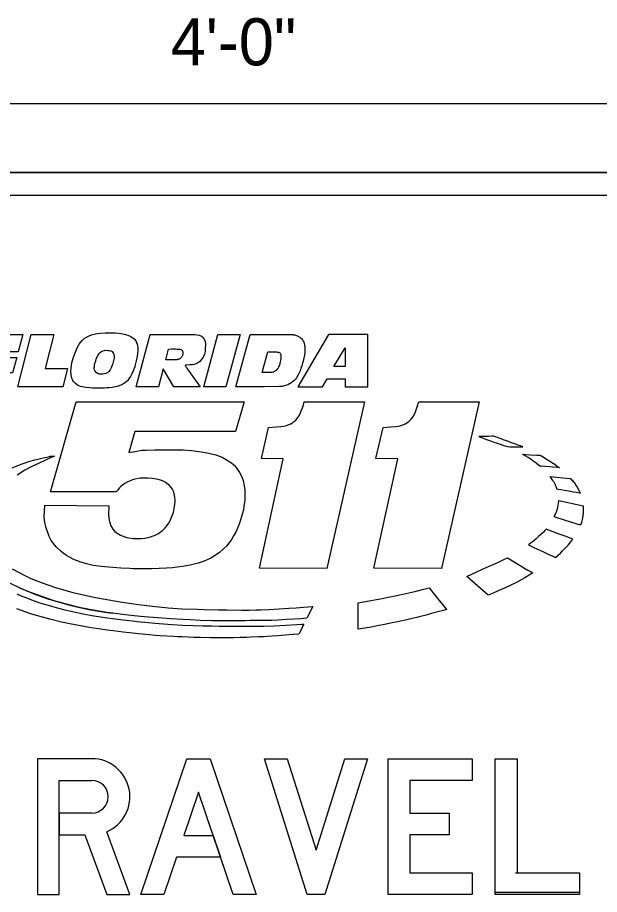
# Model space of a CAD drawing. Extents: x 0 to 770, y 0 to 495.
# Drawn here: x 288.4 to 331.6, y 418 to 483.1 of the extents above; entities that cross this region are included whole.
import ezdxf

# ---------------------------------------------------------------- set-up
doc = ezdxf.new("R2010")
doc.units = 0
for name, color, linetype in [('Default', 7, 'Continuous'), ('GSBWFill', 7, 'Continuous'), ('GSColorFill', 7, 'Continuous'), ('GSDims', 7, 'Continuous'), ('GSOutline', 7, 'Continuous'), ('TextStructures', 7, 'Continuous')]:
    doc.layers.add(name, color=color, linetype=linetype)

msp = doc.modelspace()

# ---------------------------------------------------------------- linework, layer by layer
at = {"layer": 'Default'}
for p, q in [((341.543, 471.587), (270.202, 471.587)), ((270.202, 471.587), (341.543, 471.587)), ((341.543, 469.888), (270.202, 469.888)), ((298.26, 459.55), (301.581, 459.55)), ((290.84, 447.861), (292.751, 454.562)), ((322.668, 454.562), (319.878, 442.183)), ((314.865, 442.202), (316.637, 450.318)), ((325.381, 419.568), (330.13, 419.568)), ((330.13, 419.568), (330.13, 418.091)), ((330.13, 418.091), (323.812, 418.091))]:
    msp.add_line(p, q, dxfattribs=at)
for points in [[(284.877, 459.55), (288.792, 459.55), (288.443, 458.266), (286.221, 458.266), (286.12, 457.838), (288.341, 457.838), (288.036, 456.702), (285.801, 456.702), (285.535, 455.679), (283.878, 455.679)], [(289.419, 459.55), (291.1, 459.55), (290.451, 457.019), (292.125, 457.019), (291.774, 455.679), (288.434, 455.679)], [(295.688, 459.671), (295.918, 459.656), (296.093, 459.636), (296.328, 459.59), (296.585, 459.512), (296.826, 459.411), (297.06, 459.241), (297.194, 459.074), (297.297, 458.846), (297.336, 458.596), (297.331, 458.404), (297.311, 458.14), (297.286, 457.939), (297.223, 457.605), (297.143, 457.296), (297.104, 457.161), (296.993, 456.852), (296.892, 456.635), (296.781, 456.434), (296.68, 456.264), (296.588, 456.148), (296.417, 455.988), (296.293, 455.903), (296.147, 455.827), (295.799, 455.699), (295.799, 455.699), (295.436, 455.63), (295.205, 455.603), (295.033, 455.588), (294.865, 455.577), (294.68, 455.569), (294.68, 455.569), (294.406, 455.565), (294.221, 455.568), (294.132, 455.571), (293.98, 455.578), (293.98, 455.578), (293.771, 455.594), (293.771, 455.594), (293.507, 455.621), (293.324, 455.646), (293.228, 455.66), (293.084, 455.697), (292.866, 455.796), (292.866, 455.796), (292.712, 455.907), (292.712, 455.907), (292.576, 456.049), (292.52, 456.143), (292.48, 456.224), (292.443, 456.313), (292.378, 456.57), (292.367, 456.833), (292.381, 457.027), (292.417, 457.293), (292.448, 457.459), (292.486, 457.622), (292.58, 457.937), (292.676, 458.198), (292.84, 458.569), (292.983, 458.832), (293.205, 459.116), (293.359, 459.246), (293.52, 459.347), (293.768, 459.47), (293.975, 459.547), (294.312, 459.626), (294.558, 459.655), (294.9, 459.68), (295.219, 459.687), (295.58, 459.678)], [(301.581, 459.55), (301.716, 459.542), (301.9, 459.504), (302.071, 459.424), (302.189, 459.32), (302.29, 459.148), (302.328, 459.024), (302.353, 458.855), (302.343, 458.44), (302.328, 458.283), (302.282, 458.091), (302.18, 457.862), (302.18, 457.862), (302.038, 457.662), (301.936, 457.558), (301.767, 457.429), (301.767, 457.429), (301.524, 457.326), (301.407, 457.312), (301.317, 457.303), (301.198, 457.293), (301.198, 457.293), (300.974, 457.281), (300.903, 457.28), (300.872, 457.279), (300.872, 457.273), (300.867, 457.257), (300.863, 457.256), (300.857, 457.25), (300.855, 457.234), (300.869, 457.211), (300.907, 457.156), (300.943, 457.105), (300.981, 457.052), (301.154, 456.808), (301.958, 455.679), (300.01, 455.679), (299.215, 456.998), (298.881, 455.679), (297.21, 455.679), (298.26, 459.55)], [(303.267, 459.55), (304.931, 459.55), (303.881, 455.679), (302.237, 455.679)], [(304.611, 455.679), (305.668, 459.55), (307.042, 459.564), (308.07, 459.56), (308.796, 459.55), (308.858, 459.546), (308.888, 459.542), (308.93, 459.536), (308.985, 459.525), (309.039, 459.511), (309.11, 459.489), (309.188, 459.458), (309.269, 459.418), (309.357, 459.364), (309.391, 459.34), (309.448, 459.289), (309.489, 459.247), (309.541, 459.184), (309.575, 459.134), (309.617, 459.063), (309.652, 458.987), (309.684, 458.891), (309.711, 458.773), (309.732, 458.638), (309.741, 458.541), (309.741, 458.341), (309.737, 458.283), (309.724, 458.16), (309.708, 458.041), (309.686, 457.91), (309.643, 457.709), (309.608, 457.575), (309.566, 457.429), (309.504, 457.226), (309.449, 457.059), (309.38, 456.868), (309.335, 456.752), (309.215, 456.503), (309.111, 456.34), (309.033, 456.236), (309.033, 456.236), (308.92, 456.121), (308.92, 456.121), (308.823, 456.039), (308.823, 456.039), (308.69, 455.944), (308.607, 455.894), (308.607, 455.894), (308.472, 455.826), (308.296, 455.758), (308.209, 455.733), (308.06, 455.701), (307.956, 455.687), (307.844, 455.68), (306.744, 455.666), (305.715, 455.665)], [(312.728, 455.679), (314.403, 455.679), (314.403, 459.55), (311.494, 459.55), (309.218, 455.679), (311.045, 455.679), (311.382, 456.255), (312.728, 456.255)], [(295.136, 458.377), (295.239, 458.358), (295.331, 458.33), (295.422, 458.29), (295.484, 458.221), (295.534, 458.139), (295.56, 458.058), (295.573, 457.94), (295.567, 457.834), (295.511, 457.529), (295.452, 457.324), (295.354, 457.076), (295.274, 456.928), (295.19, 456.81), (295.083, 456.711), (295.083, 456.711), (294.955, 456.651), (294.709, 456.606), (294.589, 456.604), (294.47, 456.615), (294.419, 456.626), (294.34, 456.656), (294.25, 456.72), (294.217, 456.755), (294.161, 456.831), (294.121, 456.919), (294.097, 457.035), (294.096, 457.095), (294.11, 457.189), (294.126, 457.276), (294.154, 457.4), (294.21, 457.606), (294.253, 457.74), (294.33, 457.928), (294.393, 458.05), (294.453, 458.138), (294.508, 458.201), (294.553, 458.243), (294.638, 458.303), (294.748, 458.351), (294.863, 458.376), (294.902, 458.381)], [(299.415, 457.67), (299.624, 458.471), (299.847, 458.48), (299.991, 458.482), (300.122, 458.48), (300.261, 458.476), (300.344, 458.471), (300.419, 458.464), (300.459, 458.455), (300.52, 458.438), (300.556, 458.423), (300.601, 458.396), (300.631, 458.366), (300.647, 458.343), (300.658, 458.322), (300.674, 458.271), (300.679, 458.246), (300.684, 458.211), (300.686, 458.165), (300.683, 458.119), (300.678, 458.087), (300.664, 458.035), (300.647, 457.994), (300.62, 457.943), (300.61, 457.929), (300.57, 457.871), (300.551, 457.847), (300.521, 457.816), (300.479, 457.777), (300.476, 457.775), (300.445, 457.751), (300.41, 457.73), (300.387, 457.718), (300.355, 457.705), (300.355, 457.705), (300.311, 457.695), (300.27, 457.688), (300.222, 457.683), (300.192, 457.68), (300.173, 457.678), (300.137, 457.676), (300.106, 457.675), (299.884, 457.674), (299.603, 457.672)], [(306.988, 458.266), (307.1, 458.267), (307.244, 458.268), (307.326, 458.269), (307.387, 458.269), (307.456, 458.267), (307.543, 458.263), (307.587, 458.26), (307.63, 458.256), (307.7, 458.248), (307.747, 458.242), (307.776, 458.238), (307.801, 458.231), (307.836, 458.215), (307.869, 458.192), (307.897, 458.162), (307.928, 458.108), (307.93, 458.102), (307.947, 458.046), (307.956, 458.003), (307.963, 457.952), (307.965, 457.902), (307.963, 457.852), (307.96, 457.817), (307.953, 457.754), (307.934, 457.627), (307.91, 457.513), (307.878, 457.393), (307.844, 457.289), (307.813, 457.205), (307.788, 457.145), (307.743, 457.058), (307.685, 456.978), (307.604, 456.893), (307.56, 456.858), (307.468, 456.799), (307.406, 456.769), (307.35, 456.748), (307.287, 456.731), (307.223, 456.722), (307.159, 456.721), (306.992, 456.721), (306.827, 456.721), (306.695, 456.721), (306.561, 456.721)], [(311.882, 457.186), (312.728, 458.575), (312.728, 457.186)], [(305.23, 454.562), (304.593, 452.346), (297.11, 452.346), (296.662, 450.798), (296.757, 450.813), (296.998, 450.849), (297.256, 450.888), (297.495, 450.925), (297.664, 450.951), (297.957, 450.96), (298.601, 450.977), (299.35, 450.988), (299.988, 450.991), (300.301, 450.99), (300.699, 450.979), (301.316, 450.925), (301.891, 450.857), (302.496, 450.764), (303.125, 450.606), (303.59, 450.44), (303.59, 450.44), (304.301, 450.017), (304.487, 449.846), (304.647, 449.669), (304.892, 449.315), (305.059, 448.969), (305.147, 448.704), (305.231, 448.303), (305.272, 447.982), (305.289, 447.639), (305.277, 447.248), (305.24, 446.924), (305.218, 446.794), (305.173, 446.522), (305.045, 446.038), (304.929, 445.676), (304.803, 445.344), (304.604, 444.882), (304.451, 444.586), (304.258, 444.278), (304.144, 444.121), (303.935, 443.866), (303.675, 443.598), (303.402, 443.361), (303.077, 443.128), (302.752, 442.936), (302.494, 442.81), (302.268, 442.717), (301.807, 442.569), (301.417, 442.468), (301.215, 442.422), (300.937, 442.365), (300.678, 442.32), (300.245, 442.261), (299.907, 442.228), (299.462, 442.202), (298.908, 442.174), (298.385, 442.157), (298.385, 442.157), (296.966, 442.158), (296.73, 442.165), (296.73, 442.165), (296.064, 442.206), (296.064, 442.206), (295.478, 442.25), (294.882, 442.303), (294.645, 442.326), (294.227, 442.369), (294.03, 442.404), (293.533, 442.518), (293.023, 442.677), (292.853, 442.739), (292.638, 442.825), (292.21, 443.037), (292.031, 443.145), (291.759, 443.332), (291.634, 443.43), (291.27, 443.778), (291.27, 443.778), (290.912, 444.262), (290.763, 444.538), (290.763, 444.538), (290.514, 445.273), (290.437, 445.62), (290.393, 445.972), (290.443, 446.874), (295.195, 446.818), (295.195, 446.818), (295.158, 446.144), (295.201, 445.768), (295.201, 445.768), (295.277, 445.499), (295.316, 445.399), (295.48, 445.098), (295.632, 444.921), (295.718, 444.844), (295.808, 444.785), (296.039, 444.655), (296.174, 444.593), (296.374, 444.519), (296.508, 444.479), (296.68, 444.439), (296.832, 444.414), (296.976, 444.399), (297.203, 444.388), (297.459, 444.388), (297.548, 444.393), (297.844, 444.428), (298.092, 444.478), (298.268, 444.525), (298.47, 444.594), (298.567, 444.632), (298.859, 444.781), (299.018, 444.886), (299.156, 444.992), (299.262, 445.086), (299.365, 445.19), (299.501, 445.35), (299.614, 445.507), (299.675, 445.61), (299.747, 445.743), (299.747, 445.743), (299.918, 446.15), (299.974, 446.33), (300.043, 446.633), (300.087, 446.96), (300.098, 447.113), (300.098, 447.281), (300.088, 447.417), (300.055, 447.639), (300.037, 447.718), (299.972, 447.912), (299.901, 448.056), (299.821, 448.181), (299.678, 448.347), (299.592, 448.423), (299.374, 448.576), (299.165, 448.68), (299.023, 448.731), (298.821, 448.787), (298.562, 448.841), (298.367, 448.867), (298.088, 448.884), (297.966, 448.892), (297.757, 448.892), (297.517, 448.875), (297.393, 448.858), (297.122, 448.803), (296.929, 448.747), (296.721, 448.67), (296.543, 448.58), (296.371, 448.479), (296.217, 448.385), (296.043, 448.247), (295.976, 448.164), (295.874, 448.041), (295.797, 447.946), (295.772, 447.915), (295.754, 447.893), (295.745, 447.884), (295.737, 447.877), (295.725, 447.869), (295.713, 447.865), (295.692, 447.862), (295.682, 447.861), (295.662, 447.861), (295.644, 447.861), (290.84, 447.861), (292.751, 454.562)], [(307.045, 452.644), (307.614, 452.685), (307.954, 452.724), (308.181, 452.756), (308.373, 452.796), (308.557, 452.859), (308.671, 452.911), (308.706, 452.93), (308.814, 452.994), (308.906, 453.059), (308.954, 453.097), (309.061, 453.193), (309.126, 453.262), (309.223, 453.381), (309.293, 453.485), (309.336, 453.561), (309.415, 453.731), (309.472, 453.882), (309.552, 454.108), (309.629, 454.339), (309.658, 454.43), (309.698, 454.562), (314.165, 454.562), (311.375, 442.183), (306.362, 442.202), (308.134, 450.318), (306.513, 450.337)], [(315.548, 452.644), (316.117, 452.685), (316.457, 452.724), (316.683, 452.756), (316.876, 452.796), (317.06, 452.859), (317.174, 452.911), (317.209, 452.93), (317.317, 452.994), (317.409, 453.058), (317.457, 453.096), (317.564, 453.193), (317.629, 453.262), (317.726, 453.381), (317.795, 453.485), (317.839, 453.561), (317.918, 453.731), (317.974, 453.882), (318.055, 454.108), (318.132, 454.339), (318.16, 454.43), (318.201, 454.562), (322.668, 454.562), (319.878, 442.183), (314.865, 442.202), (316.637, 450.318), (315.016, 450.336)], [(325.901, 451.209), (325.917, 451.21), (325.744, 451.273), (325.556, 451.342), (325.322, 451.428), (325.143, 451.493), (324.963, 451.559), (324.848, 451.601), (324.636, 451.679), (324.532, 451.717), (324.41, 451.761), (324.305, 451.8), (324.174, 451.848), (324.04, 451.897), (323.941, 451.933), (323.849, 451.967), (323.778, 451.993), (323.611, 451.99), (323.377, 451.986), (322.968, 451.979), (322.649, 451.973), (322.757, 451.934), (322.924, 451.873), (323.229, 451.762), (323.436, 451.687), (323.633, 451.615), (323.775, 451.562), (323.944, 451.501), (324.242, 451.399), (324.448, 451.332), (324.576, 451.292), (324.716, 451.249), (324.782, 451.23), (324.948, 451.219), (325.321, 451.205), (325.492, 451.203), (325.629, 451.204), (325.722, 451.205), (325.809, 451.206), (325.875, 451.208)], [(325.904, 450.656), (326.442, 450.625), (326.97, 450.594), (327.155, 450.583), (327.188, 450.581), (327.199, 450.58), (327.212, 450.578), (327.22, 450.577), (327.229, 450.575), (327.24, 450.571), (327.248, 450.568), (327.26, 450.563), (327.273, 450.557), (327.286, 450.549), (327.296, 450.543), (327.358, 450.504), (327.539, 450.392), (327.719, 450.28), (328.047, 450.077), (328.16, 450.007), (328.214, 449.973), (328.309, 449.903), (328.481, 449.775), (328.567, 449.711), (328.635, 449.661), (328.618, 449.662), (328.588, 449.664), (328.54, 449.668), (328.502, 449.671), (328.151, 449.698), (327.924, 449.715), (327.284, 449.764), (327.25, 449.768), (327.218, 449.773), (327.204, 449.777), (327.176, 449.79), (327.162, 449.8), (327.135, 449.819), (327.12, 449.831), (326.909, 449.992), (326.697, 450.154), (326.604, 450.224), (326.484, 450.303), (326.39, 450.364), (326.325, 450.405), (326.258, 450.446), (326.205, 450.479), (326.121, 450.53), (326.047, 450.573), (325.958, 450.625), (325.936, 450.638), (325.915, 450.65)], [(327.93, 449.017), (329.394, 448.863), (329.399, 448.863), (329.404, 448.863), (329.408, 448.862), (329.412, 448.862), (329.415, 448.861), (329.42, 448.861), (329.427, 448.859), (329.433, 448.858), (329.44, 448.856), (329.444, 448.855), (329.451, 448.852), (329.455, 448.851), (329.46, 448.848), (329.465, 448.845), (329.47, 448.842), (329.479, 448.836), (329.483, 448.832), (329.489, 448.827), (329.515, 448.8), (329.566, 448.744), (329.624, 448.677), (329.671, 448.62), (329.725, 448.552), (329.8, 448.451), (329.839, 448.395), (329.954, 448.216), (330.07, 447.988), (330.185, 447.762), (330.112, 447.775), (329.9, 447.811), (329.684, 447.848), (329.47, 447.885), (329.333, 447.908), (329.021, 447.962), (328.741, 448.01), (328.547, 448.043), (328.455, 448.059), (328.433, 448.122), (328.385, 448.256), (328.374, 448.288), (328.353, 448.347), (328.339, 448.384), (328.321, 448.426), (328.289, 448.495), (328.266, 448.539), (328.237, 448.589), (328.207, 448.635), (328.183, 448.671), (328.15, 448.715), (328.099, 448.785), (328.04, 448.867), (327.989, 448.936)], [(328.603, 447.215), (330.41, 446.838), (330.41, 446.607), (330.41, 446.376), (330.398, 446.245), (330.385, 446.14), (330.347, 445.904), (330.324, 445.809), (330.3, 445.709), (330.267, 445.578), (330.235, 445.476), (330.235, 445.476), (330.221, 445.45), (330.213, 445.438), (330.208, 445.431), (330.199, 445.422), (330.19, 445.414), (330.188, 445.412), (330.186, 445.411), (330.183, 445.41), (330.18, 445.409), (330.176, 445.408), (330.172, 445.408), (330.166, 445.409), (330.162, 445.41), (330.149, 445.412), (330.133, 445.417), (330.116, 445.422), (330.105, 445.426), (329.954, 445.473), (329.011, 445.771), (328.406, 445.962), (328.258, 446.008), (328.251, 446.01), (328.263, 446.037), (328.282, 446.079), (328.317, 446.159), (328.374, 446.289), (328.411, 446.373), (328.441, 446.445), (328.469, 446.527), (328.477, 446.556), (328.487, 446.594), (328.497, 446.642), (328.51, 446.707), (328.542, 446.883), (328.594, 447.163)], [(328.351, 442.986), (328.713, 443.322), (328.877, 443.483), (329.019, 443.628), (329.089, 443.702), (329.193, 443.817), (329.279, 443.913), (329.382, 444.032), (329.488, 444.157), (329.563, 444.249), (329.643, 444.348), (329.577, 444.373), (329.429, 444.428), (329.135, 444.536), (328.703, 444.695), (327.979, 444.963), (327.648, 445.085), (327.558, 444.992), (327.423, 444.857), (327.26, 444.7), (327.096, 444.548), (327.012, 444.472), (326.909, 444.384), (326.73, 444.236), (326.609, 444.139), (326.462, 444.025), (326.334, 443.93), (326.692, 443.763), (327.016, 443.611), (327.455, 443.405), (327.86, 443.216), (328.153, 443.079)], [(324.783, 442.957), (325.724, 442.398), (326.007, 442.23), (326.3, 442.056), (326.528, 441.921), (326.666, 441.839), (326.39, 441.673), (326.066, 441.479), (325.797, 441.323), (325.404, 441.116), (325.031, 440.932), (324.557, 440.715), (324.084, 440.511), (323.708, 440.348), (323.345, 440.191), (322.168, 441.229), (321.762, 441.587), (322.133, 441.755), (322.596, 441.965), (323.146, 442.214), (323.422, 442.34), (323.718, 442.474), (324.105, 442.649), (324.452, 442.806)], [(318.971, 440.734), (319.617, 439.929), (319.966, 439.493), (320.263, 439.123), (319.925, 439.033), (319.49, 438.916), (319.148, 438.824), (318.652, 438.691), (318.652, 438.691), (318.23, 438.578), (318.039, 438.527), (317.708, 438.452), (317.309, 438.363), (316.614, 438.212), (316.09, 438.103), (315.774, 438.039), (315.016, 437.889), (314.664, 437.822), (314.194, 437.74), (313.696, 437.652), (313.696, 438.111), (313.696, 438.636), (313.696, 438.941), (313.696, 439.621), (313.696, 439.621), (314.363, 439.737), (314.363, 439.737), (315.467, 439.941), (315.917, 440.029), (316.436, 440.133), (316.794, 440.208), (317.229, 440.306), (317.89, 440.462), (318.58, 440.633)]]:
    msp.add_lwpolyline(points, close=True, dxfattribs=at)
for points in [[(287.996, 449.652), (288.759, 449.935), (289.239, 450.113), (289.597, 450.212), (289.919, 450.297), (290.302, 450.39), (290.694, 450.479), (290.821, 450.506), (290.917, 450.522), (291.156, 450.522), (290.899, 450.411), (290.485, 450.227), (290, 450.005), (289.471, 449.754), (288.946, 449.468), (288.365, 449.108)], [(288.015, 442.138), (289.035, 441.604), (289.398, 441.439), (290.241, 441.097), (291.226, 440.767), (292.52, 440.396), (294.205, 440.009), (296.182, 439.661), (297.387, 439.49), (298.437, 439.367), (299.594, 439.258), (300.607, 439.186), (301.766, 439.144), (302.259, 439.129), (303.32, 439.102), (303.934, 439.09), (305.073, 439.075), (305.605, 439.082), (306.095, 439.093), (306.452, 439.104), (307.057, 439.128), (307.821, 439.167), (308.539, 439.215), (309.086, 439.252), (309.635, 439.29), (310.339, 439.337), (309.881, 438.47), (309.442, 438.441), (308.386, 438.372), (307.754, 438.33), (307.255, 438.32), (306.589, 438.309), (306.195, 438.304), (305.679, 438.298), (305.298, 438.295), (304.351, 438.29), (303.341, 438.291), (302.836, 438.293), (301.959, 438.319), (301.243, 438.348), (300.679, 438.375), (299.75, 438.431), (299.152, 438.473), (298.132, 438.556), (297.541, 438.611), (296.849, 438.681), (296.404, 438.73), (295.472, 438.841), (295.033, 438.9), (294.019, 439.065), (293.097, 439.253), (291.944, 439.539), (291.488, 439.668), (291.114, 439.78), (290.275, 440.057), (289.797, 440.229), (289.119, 440.493), (289.119, 440.493), (288.589, 440.714), (288.55, 440.731), (287.832, 441.079)], [(288.34, 440.282), (288.713, 440.124), (289.009, 440.005), (289.436, 439.843), (289.843, 439.698), (290.213, 439.576), (290.672, 439.435), (290.92, 439.364), (291.454, 439.219), (291.928, 439.1), (292.385, 438.993), (292.799, 438.901), (293.405, 438.778), (293.933, 438.681), (294.425, 438.599), (294.876, 438.532), (295.665, 438.424), (296.242, 438.352), (296.931, 438.272), (297.284, 438.234), (298.13, 438.151), (298.589, 438.11), (298.909, 438.084), (299.893, 438.013), (300.656, 437.968), (301.442, 437.931), (302.174, 437.911), (302.833, 437.9), (303.386, 437.893), (304.279, 437.884), (304.536, 437.883), (304.995, 437.881), (305.678, 437.88), (306.174, 437.881), (306.699, 437.888), (307.43, 437.919), (308.314, 437.961), (309.152, 438.004), (309.512, 438.024), (309.668, 438.033), (309.599, 437.9), (309.477, 437.665), (309.285, 437.297), (308.842, 437.26), (308.286, 437.217), (307.737, 437.176), (307.321, 437.146), (306.94, 437.12), (306.661, 437.102), (306.322, 437.085), (305.734, 437.061), (305.412, 437.05), (304.93, 437.036), (304.456, 437.027), (303.901, 437.021), (303.274, 437.019), (302.72, 437.023), (301.996, 437.036), (301.522, 437.049), (301.063, 437.065), (300.631, 437.083), (300.272, 437.1), (299.972, 437.116), (299.496, 437.145), (299.005, 437.178), (298.653, 437.204), (298.172, 437.243), (297.388, 437.315), (296.715, 437.384), (296.251, 437.437), (295.51, 437.528), (295.057, 437.587), (294.588, 437.653), (294.411, 437.679), (294.037, 437.735), (293.732, 437.784), (292.815, 437.951), (292.166, 438.084), (291.662, 438.196), (290.891, 438.384), (290.259, 438.551), (289.809, 438.678), (289.366, 438.809), (288.966, 438.945), (288.351, 439.17)]]:
    msp.add_lwpolyline(points, dxfattribs=at)
msp.add_arc((298.588, 463.875), 25.227, 246.5524, 262.9043, dxfattribs=at)
at = {"layer": 'GSBWFill'}
msp.add_line((291.503, 426.427), (293.924, 426.427), dxfattribs=at)
for points in [[(293.924, 428.04), (289.89, 428.04), (289.89, 417.955), (291.503, 417.955), (291.503, 426.427)], [(293.924, 424.006), (291.504, 424.006), (291.504, 422.392), (293.398, 422.392), (295.029, 417.955), (296.748, 417.955), (295.033, 422.619)]]:
    msp.add_lwpolyline(points, dxfattribs=at)
for points in [[(297.555, 417.955), (300.984, 428.04), (302.698, 428.04), (306.127, 417.955), (304.423, 417.955), (301.841, 425.549), (300.75, 422.341), (302.931, 422.341), (303.48, 420.727), (300.202, 420.727), (299.259, 417.955)], [(308.424, 428.04), (310.565, 421.245), (312.705, 428.04), (314.397, 428.04), (311.22, 417.955), (309.909, 417.955), (306.732, 428.04)], [(322.163, 426.427), (317.524, 426.427), (317.524, 424.006), (320.456, 424.006), (320.456, 422.392), (317.524, 422.392), (317.524, 419.568), (322.163, 419.568), (322.163, 417.955), (315.91, 417.955), (315.91, 428.04), (322.163, 428.04)], [(325.491, 419.568), (330.13, 419.568), (330.13, 417.955), (323.878, 417.955), (323.878, 428.04), (325.491, 428.04)]]:
    msp.add_lwpolyline(points, close=True, dxfattribs=at)
for radius, start in [(2.824, 293.1324), (1.21, 270)]:
    msp.add_arc((293.924, 425.216), radius, start, 90, dxfattribs=at)
at = {"layer": 'GSColorFill'}
msp.add_line((291.503, 426.427), (293.924, 426.427), dxfattribs=at)
for points in [[(293.924, 428.04), (289.89, 428.04), (289.89, 417.955), (291.503, 417.955), (291.503, 426.427)], [(293.924, 424.006), (291.504, 424.006), (291.504, 422.392), (293.398, 422.392), (295.029, 417.955), (296.748, 417.955), (295.033, 422.619)]]:
    msp.add_lwpolyline(points, dxfattribs=at)
for points in [[(297.555, 417.955), (300.984, 428.04), (302.698, 428.04), (306.127, 417.955), (304.423, 417.955), (301.841, 425.549), (300.75, 422.341), (302.931, 422.341), (303.48, 420.727), (300.202, 420.727), (299.259, 417.955)], [(308.424, 428.04), (310.565, 421.245), (312.705, 428.04), (314.397, 428.04), (311.22, 417.955), (309.909, 417.955), (306.732, 428.04)], [(322.163, 426.427), (317.524, 426.427), (317.524, 424.006), (320.456, 424.006), (320.456, 422.392), (317.524, 422.392), (317.524, 419.568), (322.163, 419.568), (322.163, 417.955), (315.91, 417.955), (315.91, 428.04), (322.163, 428.04)], [(325.491, 419.568), (330.13, 419.568), (330.13, 417.955), (323.878, 417.955), (323.878, 428.04), (325.491, 428.04)]]:
    msp.add_lwpolyline(points, close=True, dxfattribs=at)
for radius, start in [(2.824, 293.1324), (1.21, 270)]:
    msp.add_arc((293.924, 425.216), radius, start, 90, dxfattribs=at)
at = {"layer": 'GSDims'}
msp.add_line((265.106, 476.725), (346.638, 476.725), dxfattribs=at)
at = {"layer": 'GSOutline'}
msp.add_line((296.748, 417.955), (295.033, 422.619), dxfattribs=at)
for points in [[(293.924, 428.04), (289.89, 428.04), (289.89, 417.955), (291.503, 417.955), (291.503, 422.392), (293.398, 422.392), (295.029, 417.955), (296.748, 417.955)], [(293.924, 424.006), (291.503, 424.006), (291.503, 426.427), (293.924, 426.427)]]:
    msp.add_lwpolyline(points, dxfattribs=at)
for points in [[(300.202, 420.727), (299.259, 417.955), (297.555, 417.955), (300.984, 428.04), (302.698, 428.04), (306.127, 417.955), (304.423, 417.955), (303.48, 420.727)], [(308.424, 428.04), (310.565, 421.245), (312.705, 428.04), (314.397, 428.04), (311.22, 417.955), (309.909, 417.955), (306.732, 428.04)], [(322.163, 426.427), (317.524, 426.427), (317.524, 424.006), (320.456, 424.006), (320.456, 422.392), (317.524, 422.392), (317.524, 419.568), (322.163, 419.568), (322.163, 417.955), (315.91, 417.955), (315.91, 428.04), (322.163, 428.04)], [(325.491, 419.568), (330.13, 419.568), (330.13, 417.955), (323.878, 417.955), (323.878, 428.04), (325.491, 428.04)], [(300.75, 422.341), (302.932, 422.341), (301.841, 425.549)]]:
    msp.add_lwpolyline(points, close=True, dxfattribs=at)
for radius, start in [(2.824, 293.1324), (1.21, 270)]:
    msp.add_arc((293.924, 425.216), radius, start, 90, dxfattribs=at)

# ---------------------------------------------------------------- texts
at = {"layer": 'TextStructures'}
msp.add_text('4\'-0"', height=3.5, dxfattribs=at).set_placement((299.778, 479.55))

doc.saveas('drawing.dxf')
